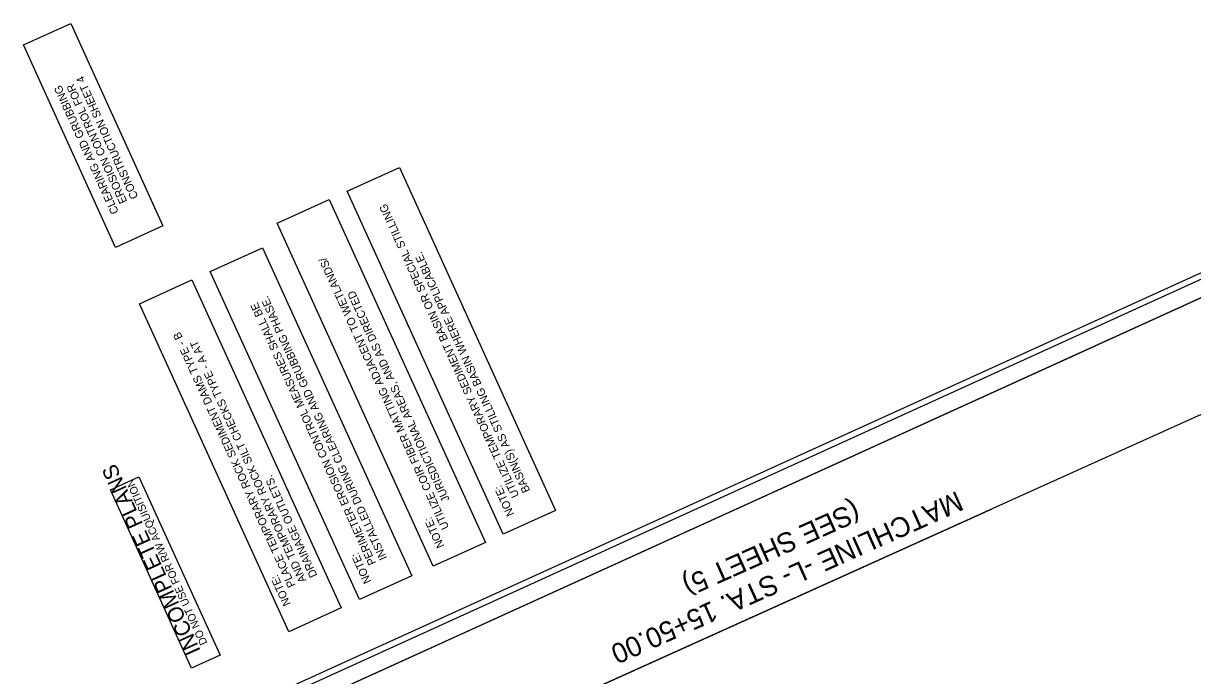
# Model space of a CAD drawing. Extents: x 2097233 to 2098987, y 683915 to 686009.
# Drawn here: x 2097233 to 2098110, y 685520 to 686009 of the extents above; entities that cross this region are included whole.
import ezdxf

# ---------------------------------------------------------------- set-up
doc = ezdxf.new("R2010")
doc.units = 0
for name, color, linetype in [('Construction Sheet Number Note CG CELL', 7, 'Continuous'), ('Matchline', 7, 'Continuous'), ('Matchline Text', 7, 'Continuous'), ('Sediment Dams and Silt Check Note CG CELL', 7, 'Continuous'), ('Sheet Layout Plan Border', 7, 'Continuous'), ('Sheet Plan CELL', 7, 'Continuous'), ('Sheet Plot Border Inside CELL', 7, 'Continuous'), ('Sheet Plot Border Outside CELL', 7, 'Continuous'), ('Sheet Sticker Incomplete CELL', 7, 'Continuous')]:
    doc.layers.add(name, color=color, linetype=linetype)

# ---------------------------------------------------------------- blocks, each defined once
blk = doc.blocks.new('CGNT2')
at = {"layer": 'Sediment Dams and Silt Check Note CG CELL'}
blk.add_lwpolyline([(-2.704, 0.431), (2.704, 0.43125), (2.704, -0.43), (-2.704, -0.43)], close=True, dxfattribs=at)
for s, p in [('NOTE:', (-2.335, 0.231)), ('     PLACE TEMPORARY ROCK SEDIMENT DAMS TYPE - B', (-2.335, 0.05125)), ('     AND TEMPORARY ROCK SILT CHECKS TYPE - A AT', (-2.335, -0.129)), ('     DRAINAGE OUTLETS.', (-2.335, -0.309))]:
    blk.add_text(s, height=0.12, dxfattribs=at).set_placement(p)

msp = doc.modelspace()

# ---------------------------------------------------------------- linework, layer by layer
at = {"layer": 'Construction Sheet Number Note CG CELL'}
for points in [[(2097592.95, 685625.9), (2097475.86, 685883.2), (2097515.05, 685901.03), (2097632.13, 685643.73)], [(2097540.41, 685601.99), (2097423.32, 685859.29), (2097462.51, 685877.12), (2097579.59, 685619.82)]]:
    msp.add_lwpolyline(points, close=True, dxfattribs=at)
at = {"layer": 'Matchline'}
msp.add_line((2097640.09, 685500.72), (2097959.09, 685644.72), dxfattribs=at)
at = {"layer": 'Sediment Dams and Silt Check Note CG CELL'}
for points in [[(2097302.2, 685841.13), (2097233.09, 685993.05), (2097268.59, 686009.2), (2097337.71, 685857.29)], [(2097485.21, 685576.87), (2097373.22, 685822.99), (2097412.4, 685840.82), (2097524.4, 685594.71)]]:
    msp.add_lwpolyline(points, close=True, dxfattribs=at)
at = {"layer": 'Sheet Layout Plan Border'}
msp.add_lwpolyline([(2098897.26, 684510.8), (2097955.44, 684082.23), (2097499.89, 685083.35), (2097523.79, 685094.22), (2097440.93, 685276.32), (2097563.62, 685332.14), (2097512.93, 685443.54), (2098309.25, 685803.01)], close=True, dxfattribs=at)
at = {"layer": 'Sheet Plan CELL'}
for points in [[(2097320.28, 685441.22), (2097941.56, 684075.89), (2098897.27, 684510.77), (2098276, 685876.08)], [(2098897.27, 684510.77), (2097941.59, 684075.88), (2097403.14, 685259.11), (2097539.72, 685321.27), (2097456.88, 685503.35), (2098276, 685876.08)]]:
    msp.add_lwpolyline(points, close=True, dxfattribs=at)
at = {"layer": 'Sheet Plot Border Inside CELL'}
msp.add_lwpolyline([(2098963.13, 684372.11), (2098273.1, 685888.48), (2097312.85, 685451.54), (2098002.87, 683935.16)], close=True, dxfattribs=at)
at = {"layer": 'Sheet Plot Border Outside CELL'}
msp.add_lwpolyline([(2098986.71, 684368.56), (2098289.45, 685900.88), (2097292.78, 685447.36), (2097990.05, 683915.04)], close=True, dxfattribs=at)
at = {"layer": 'Sheet Sticker Incomplete CELL'}
msp.add_lwpolyline([(2097380.58, 685535.21), (2097359.19, 685525.48), (2097298.31, 685659.28), (2097319.7, 685669.01)], close=True, dxfattribs=at)

# ---------------------------------------------------------------- block references
at = {"layer": 'Sediment Dams and Silt Check Note CG CELL', "xscale": 50.000000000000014, "yscale": 49.99999999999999, "rotation": 114.46741583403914}
msp.add_blockref('CGNT2', (2097395.86, 685684.76), dxfattribs=at)

# ---------------------------------------------------------------- texts
at = {"layer": 'Construction Sheet Number Note CG CELL'}
for s, p in [('     UTILIZE TEMPORARY SEDIMENT BASIN OR SPECIAL STILLING', (2097609.64, 685644.76)), ('     BASIN(S) AS STILLING BASIN WHERE APPLICABLE.', (2097617.82, 685648.49)), ('     UTILIZE COIR FIBER MATTING ADJACENT TO WETLANDS/', (2097557.09, 685620.85)), ('JURISDICTIONAL AREAS, AND AS DIRECTED', (2097552.86, 685651.89)), ('NOTE:  ', (2097601.44, 685641.04)), ('NOTE:  ', (2097548.9, 685617.13))]:
    msp.add_text(s, height=6, rotation=114.46742, dxfattribs=at).set_placement(p)
at = {"layer": 'Matchline Text'}
for s, p in [('MATCHLINE -L- STA. 15+50.00', (2097933.24, 685658.61)), ('(SEE SHEET 5)', (2097856.29, 685650.86))]:
    msp.add_text(s, height=15, rotation=204.12202, dxfattribs=at).set_placement(p)
at = {"layer": 'Sediment Dams and Silt Check Note CG CELL'}
for s, p in [('CONSTRUCTION SHEET 4', (2097319.39, 685878.97)), ('CLEARING AND GRUBBING', (2097304.74, 685867.69)), ('EROSION CONTROL FOR', (2097311.03, 685875.61)), ('     PERIMETER EROSION CONTROL MEASURES SHALL BE', (2097502.36, 685594.24)), ('     INSTALLED DURING CLEARING AND GRUBBING PHASE.', (2097510.55, 685597.96)), ('NOTE:', (2097494.17, 685590.51))]:
    msp.add_text(s, height=6, rotation=114.46742, dxfattribs=at).set_placement(p)
at = {"layer": 'Sheet Sticker Incomplete CELL'}
for s, height, p in [('INCOMPLETE PLANS', 11.52, (2097366.22, 685538.51)), ('DO NOT USE FOR R/W ACQUISITION', 5.76, (2097371.2, 685544.35))]:
    msp.add_text(s, height=height, rotation=114.46742, dxfattribs=at).set_placement(p)

doc.saveas('drawing.dxf')
